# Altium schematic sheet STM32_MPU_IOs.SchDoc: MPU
size A3; SheetNumber: 3; SheetTotal: 7
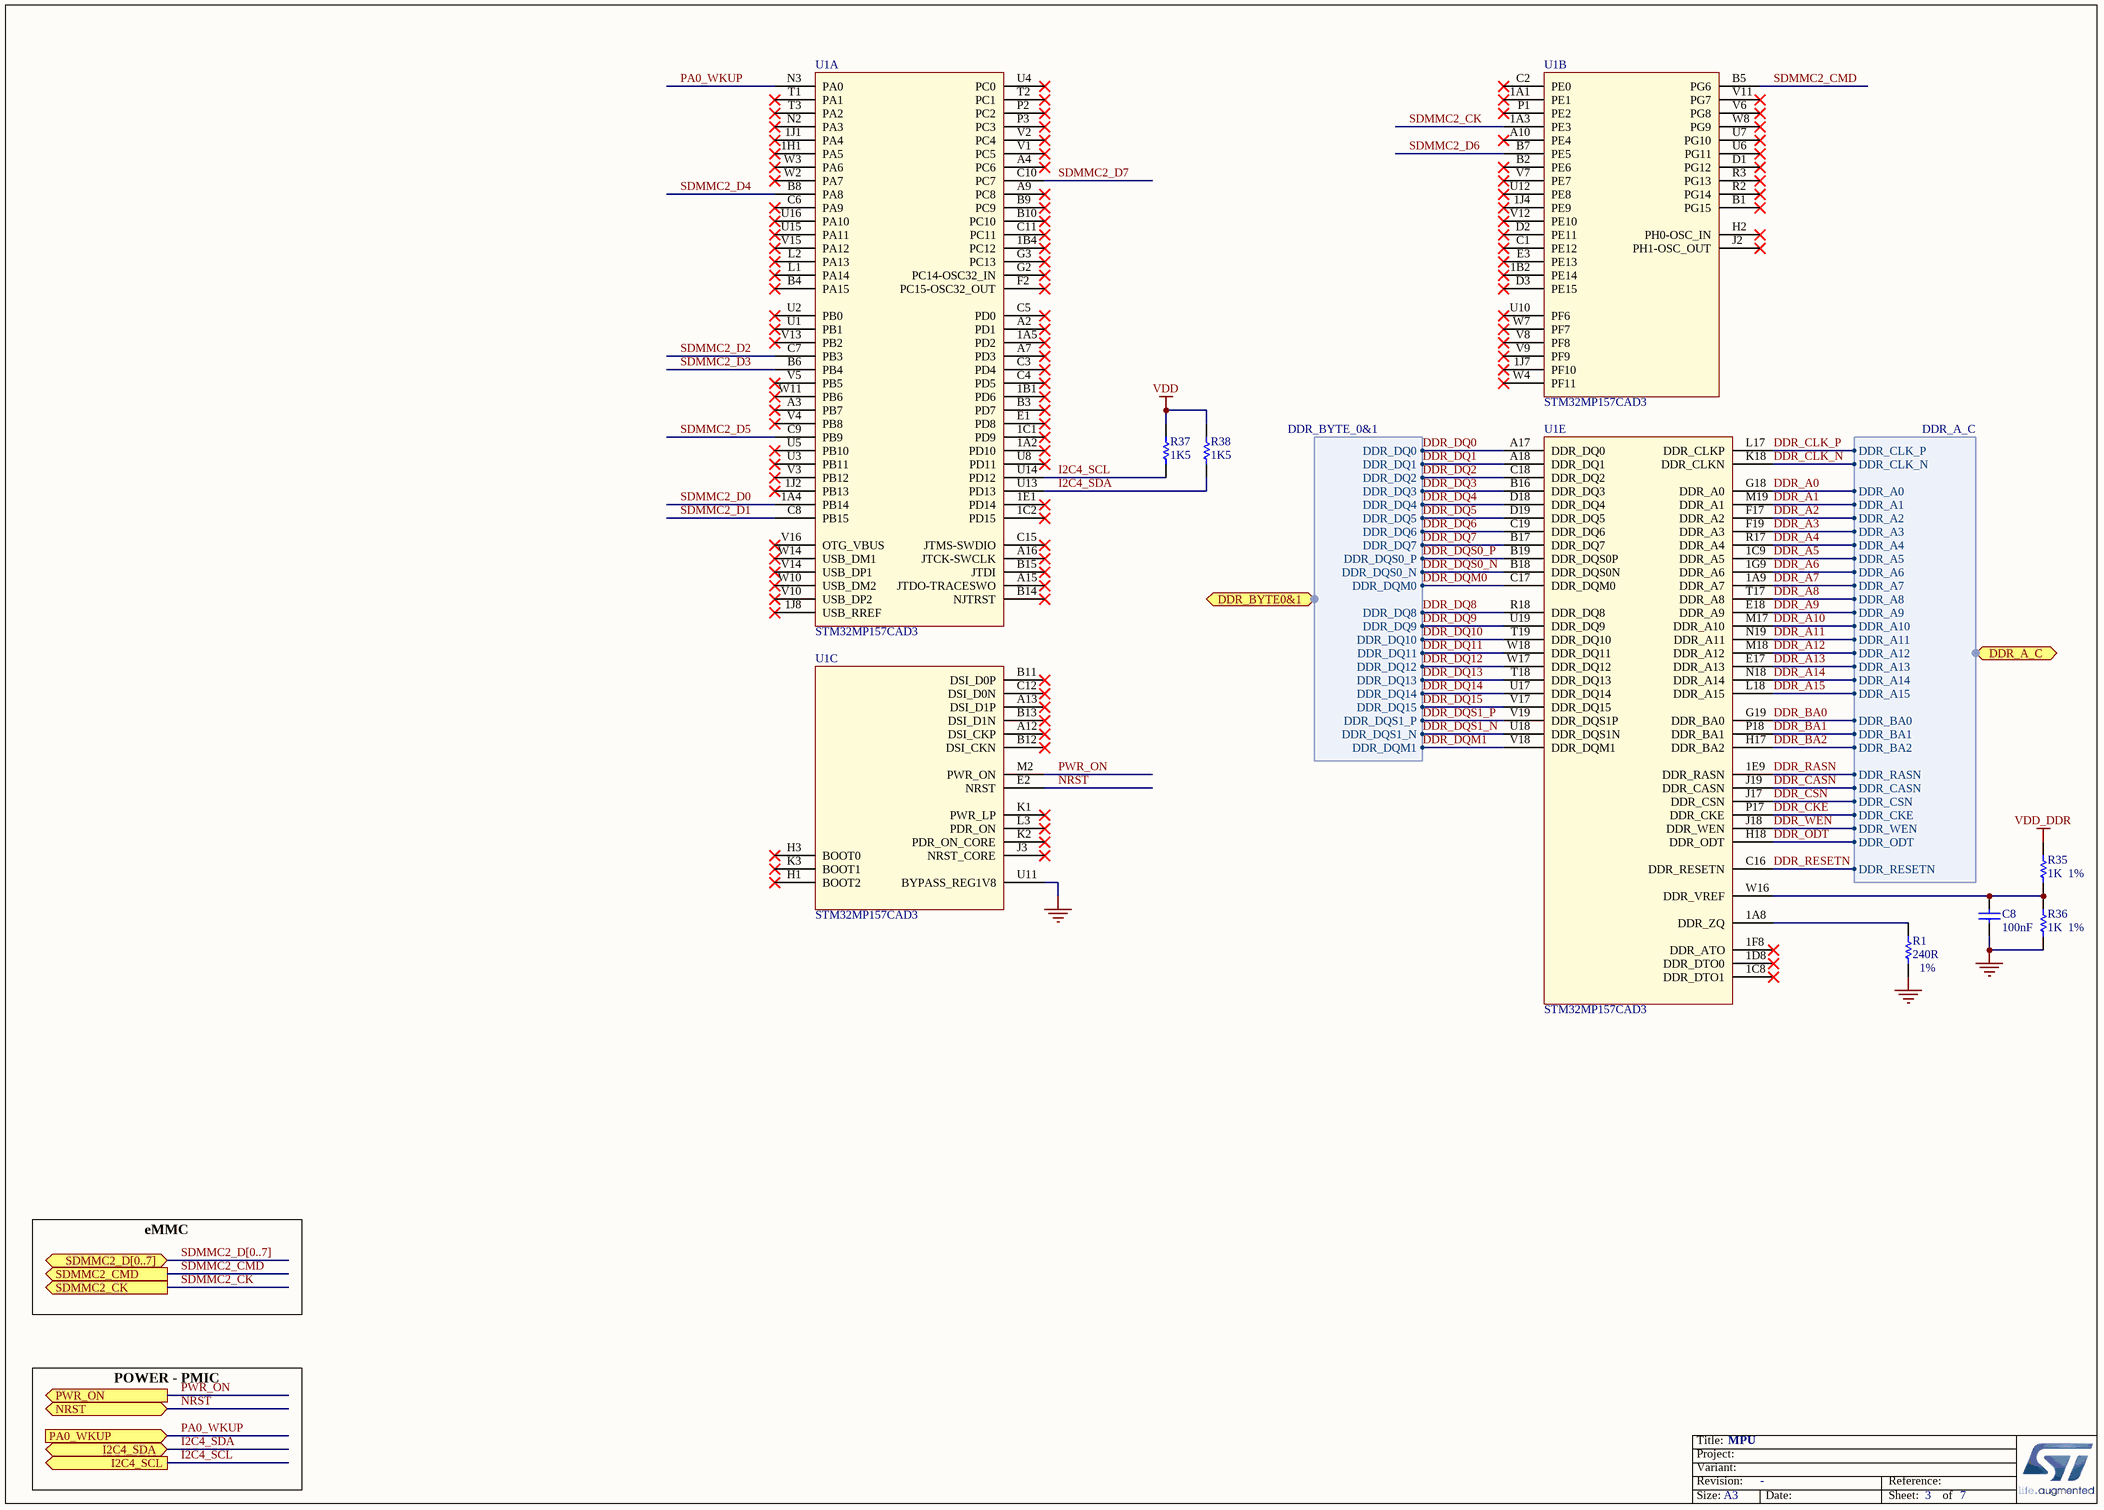
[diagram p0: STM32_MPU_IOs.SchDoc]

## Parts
C8  value 100nF  [C0402]
R1  value 240R  [R0402]
R35  value 1K  [R0402]
R36  value 1K  [R0402]
R37  value 1K5  [R0402]
R38  value 1K5  [R0402]
U1  value STM32MP157CAD3  [ICC_TFBGA257_10X10_STM32MP157CAD3_P050-065]  (parts A,B,C,E of 5)

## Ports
DDR_A_C (harness DDR_A_C), DDR_BYTE0&1 (harness DDR_BYTE_0&1), I2C4_SCL (out), I2C4_SDA (bidir), NRST (bidir), PA0_WKUP (in), PWR_ON (out), SDMMC2_CK (out), SDMMC2_CMD (out), SDMMC2_D[0..7] (bidir)

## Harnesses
DDR_BYTE_0&1: DDR_DQ0, DDR_DQ1, DDR_DQ2, DDR_DQ3, DDR_DQ4, DDR_DQ5, DDR_DQ6, DDR_DQ7, DDR_DQS0_P, DDR_DQS0_N, DDR_DQM0, DDR_DQ8, DDR_DQ9, DDR_DQ10, DDR_DQ11, DDR_DQ12, DDR_DQ13, DDR_DQ14, DDR_DQ15, DDR_DQS1_P, DDR_DQS1_N, DDR_DQM1
DDR_A_C: DDR_CLK_P, DDR_CLK_N, DDR_A0, DDR_A1, DDR_A2, DDR_A3, DDR_A4, DDR_A5, DDR_A6, DDR_A7, DDR_A8, DDR_A9, DDR_A10, DDR_A11, DDR_A12, DDR_A13, DDR_A14, DDR_BA0, DDR_BA1, DDR_BA2, DDR_RASN, DDR_CASN, DDR_CSN, DDR_CKE, DDR_WEN, DDR_ODT, DDR_RESETN, DDR_A15

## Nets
GND: C8.1 R1.1 R36.1 U1.U11(BYPASS_REG1V8)
VDD: R37.1 R38.1
VDD_DDR: R35.2
DDR_A0: U1.G18(DDR_A0) ; port DDR_A_C.DDR_A0
DDR_A1: U1.M19(DDR_A1) ; port DDR_A_C.DDR_A1
DDR_A2: U1.F17(DDR_A2) ; port DDR_A_C.DDR_A2
DDR_A3: U1.F19(DDR_A3) ; port DDR_A_C.DDR_A3
DDR_A4: U1.R17(DDR_A4) ; port DDR_A_C.DDR_A4
DDR_A5: U1.1C9(DDR_A5) ; port DDR_A_C.DDR_A5
DDR_A6: U1.1G9(DDR_A6) ; port DDR_A_C.DDR_A6
DDR_A7: U1.1A9(DDR_A7) ; port DDR_A_C.DDR_A7
DDR_A8: U1.T17(DDR_A8) ; port DDR_A_C.DDR_A8
DDR_A9: U1.E18(DDR_A9) ; port DDR_A_C.DDR_A9
DDR_A10: U1.M17(DDR_A10) ; port DDR_A_C.DDR_A10
DDR_A11: U1.N19(DDR_A11) ; port DDR_A_C.DDR_A11
DDR_A12: U1.M18(DDR_A12) ; port DDR_A_C.DDR_A12
DDR_A13: U1.E17(DDR_A13) ; port DDR_A_C.DDR_A13
DDR_A14: U1.N18(DDR_A14) ; port DDR_A_C.DDR_A14
DDR_A15: U1.L18(DDR_A15) ; port DDR_A_C.DDR_A15
DDR_BA0: U1.G19(DDR_BA0) ; port DDR_A_C.DDR_BA0
DDR_BA1: U1.P18(DDR_BA1) ; port DDR_A_C.DDR_BA1
DDR_BA2: U1.H17(DDR_BA2) ; port DDR_A_C.DDR_BA2
DDR_CASN: U1.J19(DDR_CASN) ; port DDR_A_C.DDR_CASN
DDR_CKE: U1.P17(DDR_CKE) ; port DDR_A_C.DDR_CKE
DDR_CLK_N: U1.K18(DDR_CLKN) ; port DDR_A_C.DDR_CLK_N
DDR_CLK_P: U1.L17(DDR_CLKP) ; port DDR_A_C.DDR_CLK_P
DDR_CSN: U1.J17(DDR_CSN) ; port DDR_A_C.DDR_CSN
DDR_DQ0: U1.A17(DDR_DQ0) ; port DDR_BYTE0&1.DDR_DQ0
DDR_DQ1: U1.A18(DDR_DQ1) ; port DDR_BYTE0&1.DDR_DQ1
DDR_DQ2: U1.C18(DDR_DQ2) ; port DDR_BYTE0&1.DDR_DQ2
DDR_DQ3: U1.B16(DDR_DQ3) ; port DDR_BYTE0&1.DDR_DQ3
DDR_DQ4: U1.D18(DDR_DQ4) ; port DDR_BYTE0&1.DDR_DQ4
DDR_DQ5: U1.D19(DDR_DQ5) ; port DDR_BYTE0&1.DDR_DQ5
DDR_DQ6: U1.C19(DDR_DQ6) ; port DDR_BYTE0&1.DDR_DQ6
DDR_DQ7: U1.B17(DDR_DQ7) ; port DDR_BYTE0&1.DDR_DQ7
DDR_DQ8: U1.R18(DDR_DQ8) ; port DDR_BYTE0&1.DDR_DQ8
DDR_DQ9: U1.U19(DDR_DQ9) ; port DDR_BYTE0&1.DDR_DQ9
DDR_DQ10: U1.T19(DDR_DQ10) ; port DDR_BYTE0&1.DDR_DQ10
DDR_DQ11: U1.W18(DDR_DQ11) ; port DDR_BYTE0&1.DDR_DQ11
DDR_DQ12: U1.W17(DDR_DQ12) ; port DDR_BYTE0&1.DDR_DQ12
DDR_DQ13: U1.T18(DDR_DQ13) ; port DDR_BYTE0&1.DDR_DQ13
DDR_DQ14: U1.U17(DDR_DQ14) ; port DDR_BYTE0&1.DDR_DQ14
DDR_DQ15: U1.V17(DDR_DQ15) ; port DDR_BYTE0&1.DDR_DQ15
DDR_DQM0: U1.C17(DDR_DQM0) ; port DDR_BYTE0&1.DDR_DQM0
DDR_DQM1: U1.V18(DDR_DQM1) ; port DDR_BYTE0&1.DDR_DQM1
DDR_DQS0_N: U1.B18(DDR_DQS0N) ; port DDR_BYTE0&1.DDR_DQS0_N
DDR_DQS0_P: U1.B19(DDR_DQS0P) ; port DDR_BYTE0&1.DDR_DQS0_P
DDR_DQS1_N: U1.U18(DDR_DQS1N) ; port DDR_BYTE0&1.DDR_DQS1_N
DDR_DQS1_P: U1.V19(DDR_DQS1P) ; port DDR_BYTE0&1.DDR_DQS1_P
DDR_ODT: U1.H18(DDR_ODT) ; port DDR_A_C.DDR_ODT
DDR_RASN: U1.1E9(DDR_RASN) ; port DDR_A_C.DDR_RASN
DDR_RESETN: U1.C16(DDR_RESETN) ; port DDR_A_C.DDR_RESETN
DDR_WEN: U1.J18(DDR_WEN) ; port DDR_A_C.DDR_WEN
I2C4_SCL: R37.2 U1.U14(PD12) ; port I2C4_SCL
I2C4_SDA: R38.2 U1.U13(PD13) ; port I2C4_SDA
NRST: U1.E2(NRST) ; port NRST
PA0_WKUP: U1.N3(PA0) ; port PA0_WKUP
PWR_ON: U1.M2(PWR_ON) ; port PWR_ON
SDMMC2_CK: U1.1A3(PE3) ; port SDMMC2_CK
SDMMC2_CMD: U1.B5(PG6) ; port SDMMC2_CMD
SDMMC2_D0: U1.1A4(PB14)
SDMMC2_D1: U1.C8(PB15)
SDMMC2_D2: U1.C7(PB3)
SDMMC2_D3: U1.B6(PB4)
SDMMC2_D4: U1.B8(PA8)
SDMMC2_D5: U1.C9(PB9)
SDMMC2_D6: U1.B7(PE5)
SDMMC2_D7: U1.C10(PC7)
NetC8_2: C8.2 R35.1 R36.2 U1.W16(DDR_VREF)
NetR1_2: R1.2 U1.1A8(DDR_ZQ)

Not connected (* = marked no-connect by the designer): U1 1A1(PE1)* 1A2(PD10)* 1A5(PD2)* 1B1(PD6)* 1B2(PE14)* 1B4(PC12)* 1C1(PD9)* 1C2(PD15)* 1C8(DDR_DTO1)* 1D8(DDR_DTO0)* 1E1(PD14)* 1F8(DDR_ATO)* 1H1(PA5)* 1J1(PA4)* 1J2(PB13)* 1J4(PE9)* 1J7(PF10)* 1J8(USB_RREF)* A2(PD1)* A3(PB7)* A4(PC6)* A7(PD3)* A9(PC8)* A10(PE4)* A12(DSI_CKP)* A13(DSI_D1P)* A15(JTDO-TRACESWO)* A16(JTCK-SWCLK)* B1(PG15)* B2(PE6)* B3(PD7)* B4(PA15)* B9(PC9)* B10(PC10)* B11(DSI_D0P)* B12(DSI_CKN)* B13(DSI_D1N)* B14(NJTRST)* B15(JTDI)* C1(PE12)* C2(PE0)* C3(PD4)* C4(PD5)* C5(PD0)* C6(PA9)* C11(PC11)* C12(DSI_D0N)* C15(JTMS-SWDIO)* D1(PG12)* D2(PE11)* D3(PE15)* E1(PD8)* E3(PE13)* F2(PC15-OSC32_OUT)* G2(PC14-OSC32_IN)* G3(PC13)* H1(BOOT2)* H2(PH0-OSC_IN)* H3(BOOT0)* J2(PH1-OSC_OUT)* J3(NRST_CORE)* K1(PWR_LP)* K2(PDR_ON_CORE)* K3(BOOT1)* L1(PA14)* L2(PA13)* L3(PDR_ON)* N2(PA3)* P1(PE2)* P2(PC2)* P3(PC3)* R2(PG14)* R3(PG13)* T1(PA1)* T2(PC1)* T3(PA2)* U1(PB1)* U2(PB0)* U3(PB11)* U4(PC0)* U5(PB10)* U6(PG11)* U7(PG10)* U8(PD11)* U10(PF6)* U12(PE8)* U15(PA11)* U16(PA10)* V1(PC5)* V2(PC4)* V3(PB12)* V4(PB8)* V5(PB5)* V6(PG8)* V7(PE7)* V8(PF8)* V9(PF9)* V10(USB_DP2)* V11(PG7)* V12(PE10)* V13(PB2)* V14(USB_DP1)* V15(PA12)* V16(OTG_VBUS)* W2(PA7)* W3(PA6)* W4(PF11)* W7(PF7)* W8(PG9)* W10(USB_DM2)* W11(PB6)* W14(USB_DM1)*

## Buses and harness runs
bus SDMMC2_D[0..7] = port SDMMC2_D[0..7]

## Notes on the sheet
- 1%
- (near R1) 1%
- (near R36) 1%
- eMMC
- POWER - PMIC

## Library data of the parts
C8 = MCD-00006: Capacitor, MLCC, 100nF, 16V, X7R, 10%, 0402, T=0.5mm; Manufacturer_Part_Number: CC0402KRX7R7BB104; Manufacturer: YAGEO; Alternate_Manufacturer_Part_Number: GCM155R71C104KA55D; Alternate_Manufacturer: MURATA; Provided_By: SUBCO; ECCN_US: EAR99; ECCN_EU: NEC
R1 = MCD-00120: Resistor,240R,0402,1%,1/16W; Manufacturer_Part_Number: RC0402FR-07240RL; Manufacturer: YAGEO; Provided_By: SUBCO; ECCN_US: EAR99; ECCN_EU: NEC
R35 R36 = MCD-00061: Resistor,1K,0402,1%,1/16W; Manufacturer_Part_Number: RC0402FR-071KL; Manufacturer: YAGEO; Provided_By: SUBCO; ECCN_US: EAR99; ECCN_EU: NEC
R37 R38 = MCD-00068: Resistor,1K5,0402,1%,1/16W; Manufacturer_Part_Number: RC0402FR-071K5L; Manufacturer: YAGEO; Provided_By: SUBCO; ECCN_US: EAR99; ECCN_EU: NEC
U1 = MCD-01144: MPU TFBGA10x10 secure boot+crypto; Part_Type: IC; Manufacturer: STMICROELECTRONICS; Provided_By: SUBCO with ST control; ECCN_US: 5A002A4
